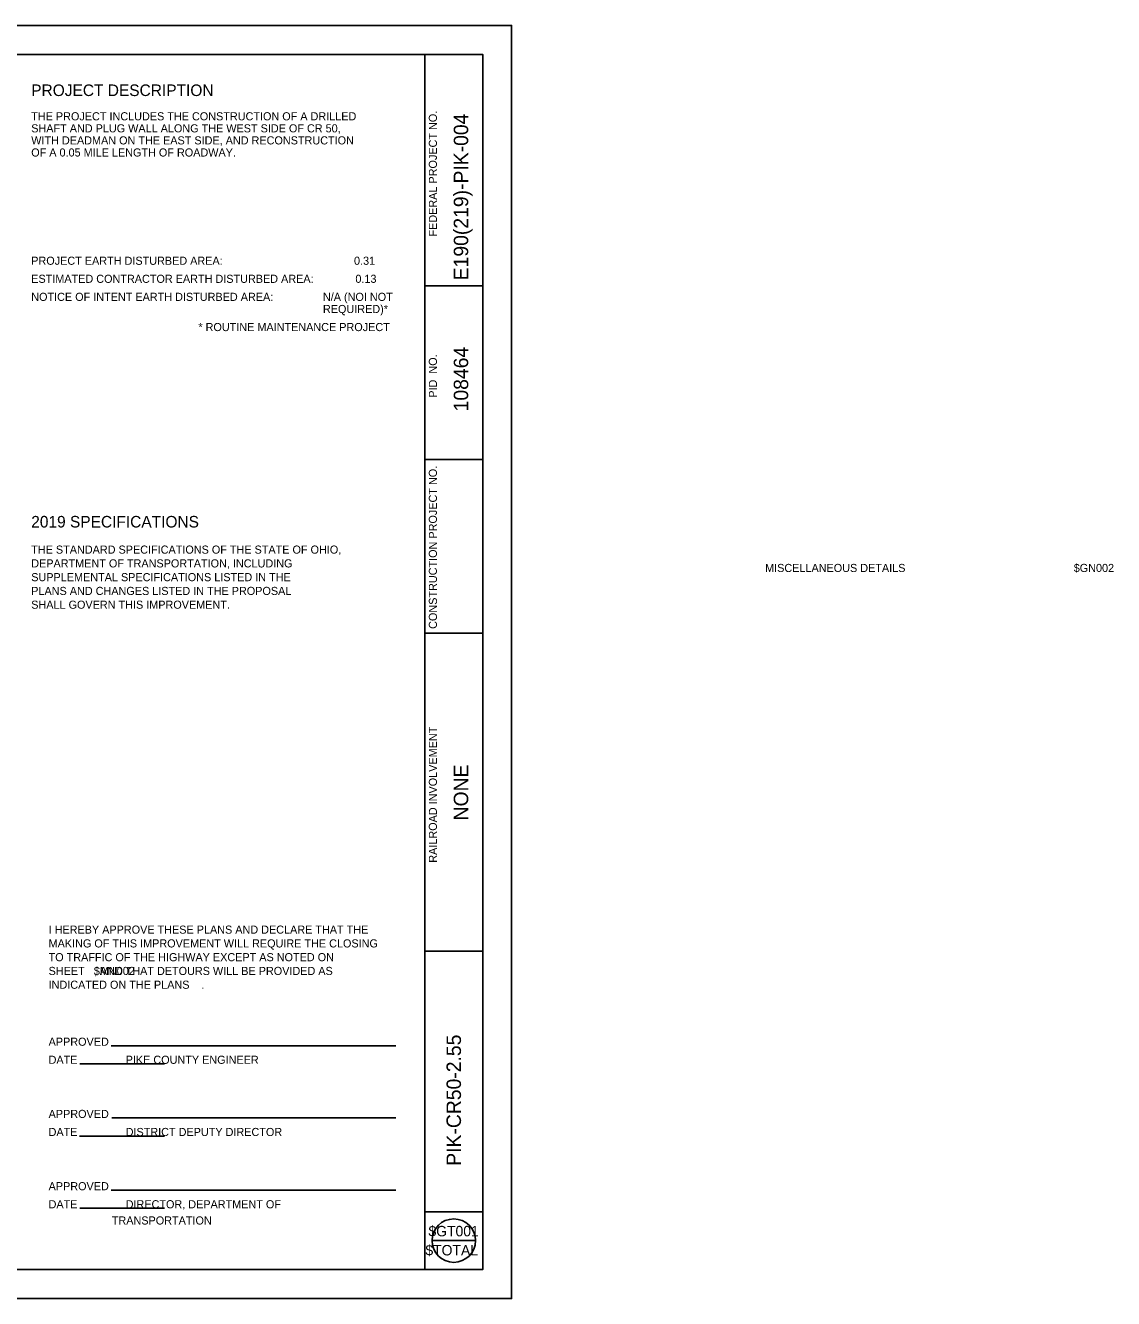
# Model space of a CAD drawing. Extents: x 1862092.2 to 1862141.4, y 420599.8 to 420643.6.
# Drawn here: x 1862122.58 to 1862141.38, y 420600.62 to 420622.62 of the extents above; entities that cross this region are included whole.
import ezdxf

# ---------------------------------------------------------------- set-up
doc = ezdxf.new("R2010")
doc.units = 0
for name, color, linetype in [('SH_Border', 7, 'Continuous'), ('SH_Cut_Line', 7, 'Continuous'), ('SH_Data', 7, 'Continuous'), ('SH_Text', 7, 'Continuous')]:
    doc.layers.add(name, color=color, linetype=linetype)

msp = doc.modelspace()

# ---------------------------------------------------------------- linework, layer by layer
at = {"layer": 'SH_Border'}
for p, q in [((1862129.479, 420601.116), (1862129.479, 420622.116)), ((1862129.479, 420618.116), (1862130.479, 420618.116)), ((1862129.479, 420615.116), (1862130.479, 420615.116)), ((1862129.479, 420612.116), (1862130.479, 420612.116)), ((1862129.479, 420606.616), (1862130.479, 420606.616)), ((1862129.479, 420602.116), (1862130.479, 420602.116))]:
    msp.add_line(p, q, dxfattribs=at)
msp.add_lwpolyline([(1862098.979, 420622.116), (1862130.479, 420622.116), (1862130.479, 420601.116), (1862098.979, 420601.116)], close=True, dxfattribs=at)
at = {"layer": 'SH_Cut_Line'}
msp.add_lwpolyline([(1862096.979, 420600.616), (1862130.979, 420600.616), (1862130.979, 420622.616), (1862096.979, 420622.616)], close=True, dxfattribs=at)
at = {"layer": 'SH_Data'}
for p, q in [((1862124.059, 420604.984), (1862128.979, 420604.984)), ((1862123.521, 420604.672), (1862124.979, 420604.672)), ((1862124.074, 420603.736), (1862128.979, 420603.736)), ((1862123.512, 420603.424), (1862124.979, 420603.424)), ((1862124.059, 420602.487), (1862128.979, 420602.487)), ((1862123.521, 420602.175), (1862124.979, 420602.175)), ((1862129.604, 420601.616), (1862130.354, 420601.616))]:
    msp.add_line(p, q, dxfattribs=at)
msp.add_circle((1862129.979, 420601.616), 0.375, dxfattribs=at)

# ---------------------------------------------------------------- texts
for s, height, p in [('PROJECT DESCRIPTION', 0.2, (1862122.679, 420621.396)), ('THE PROJECT INCLUDES THE CONSTRUCTION OF A DRILLED ', 0.14, (1862122.679, 420620.976)), ('SHAFT AND PLUG WALL ALONG THE WEST SIDE OF CR 50, ', 0.14, (1862122.679, 420620.768)), ('WITH DEADMAN ON THE EAST SIDE, AND RECONSTRUCTION ', 0.14, (1862122.679, 420620.56)), ('OF A 0.05 MILE LENGTH OF ROADWAY.', 0.14, (1862122.679, 420620.351)), ('PROJECT EARTH DISTURBED AREA:', 0.14, (1862122.679, 420618.48)), ('0.31', 0.14, (1862128.256, 420618.48)), ('ESTIMATED CONTRACTOR EARTH DISTURBED AREA:', 0.14, (1862122.679, 420618.168)), ('0.13', 0.14, (1862128.28, 420618.168)), ('N/A (NOI NOT', 0.14, (1862127.719, 420617.856)), ('NOTICE OF INTENT EARTH DISTURBED AREA:', 0.14, (1862122.679, 420617.856)), ('REQUIRED)*', 0.14, (1862127.719, 420617.646)), ('* ROUTINE MAINTENANCE PROJECT', 0.14, (1862125.567, 420617.334)), ('2019 SPECIFICATIONS', 0.2, (1862122.679, 420613.94)), ('THE STANDARD SPECIFICATIONS OF THE STATE OF OHIO,', 0.14, (1862122.679, 420613.488)), ('DEPARTMENT OF TRANSPORTATION, INCLUDING', 0.14, (1862122.679, 420613.25)), ('MISCELLANEOUS DETAILS', 0.14, (1862135.359, 420613.171)), ('$GN002', 0.14, (1862140.691, 420613.171)), ('SUPPLEMENTAL SPECIFICATIONS LISTED IN THE', 0.14, (1862122.679, 420613.012)), ('PLANS AND CHANGES LISTED IN THE PROPOSAL', 0.14, (1862122.679, 420612.774)), ('SHALL GOVERN THIS IMPROVEMENT.', 0.14, (1862122.679, 420612.536)), ('I HEREBY APPROVE THESE PLANS AND DECLARE THAT THE', 0.14, (1862122.979, 420606.921)), ('MAKING OF THIS IMPROVEMENT WILL REQUIRE THE CLOSING', 0.14, (1862122.979, 420606.683)), ('TO TRAFFIC OF THE HIGHWAY EXCEPT AS NOTED ON', 0.14, (1862122.979, 420606.445)), ('SHEET   , AND THAT DETOURS WILL BE PROVIDED AS', 0.14, (1862122.979, 420606.207)), ('INDICATED ON THE PLANS', 0.14, (1862122.979, 420605.969)), ('.', 0.14, (1862125.617, 420605.969)), ('APPROVED', 0.14, (1862122.979, 420604.984)), ('DATE                PIKE COUNTY ENGINEER', 0.14, (1862122.979, 420604.672)), ('APPROVED', 0.14, (1862122.979, 420603.736)), ('DATE                DISTRICT DEPUTY DIRECTOR', 0.14, (1862122.979, 420603.424)), ('APPROVED', 0.14, (1862122.979, 420602.487)), ('DATE                DIRECTOR, DEPARTMENT OF', 0.14, (1862122.979, 420602.175)), ('                     TRANSPORTATION', 0.14, (1862122.979, 420601.895)), ('$GT001', 0.18, (1862129.542, 420601.691)), ('$TOTAL', 0.18, (1862129.489, 420601.361))]:
    msp.add_text(s, height=height, dxfattribs=at).set_placement(p)
for s, height, p in [('FEDERAL PROJECT NO.', 0.14, (1862129.689, 420618.968)), ('E190(219)-PIK-004', 0.25, (1862130.229, 420618.212)), ('PID  NO.', 0.14, (1862129.689, 420616.183)), ('108464', 0.25, (1862130.229, 420615.947)), ('CONSTRUCTION PROJECT NO.', 0.14, (1862129.689, 420612.188)), ('RAILROAD INVOLVEMENT', 0.14, (1862129.689, 420608.147)), ('NONE', 0.25, (1862130.229, 420608.878)), ('PIK-CR50-2.55', 0.25, (1862130.104, 420602.91))]:
    msp.add_text(s, height=height, rotation=90, dxfattribs=at).set_placement(p)
at = {"layer": 'SH_Text'}
msp.add_text('$MN002', height=0.14, dxfattribs=at).set_placement((1862123.761, 420606.207))

doc.saveas('drawing.dxf')
